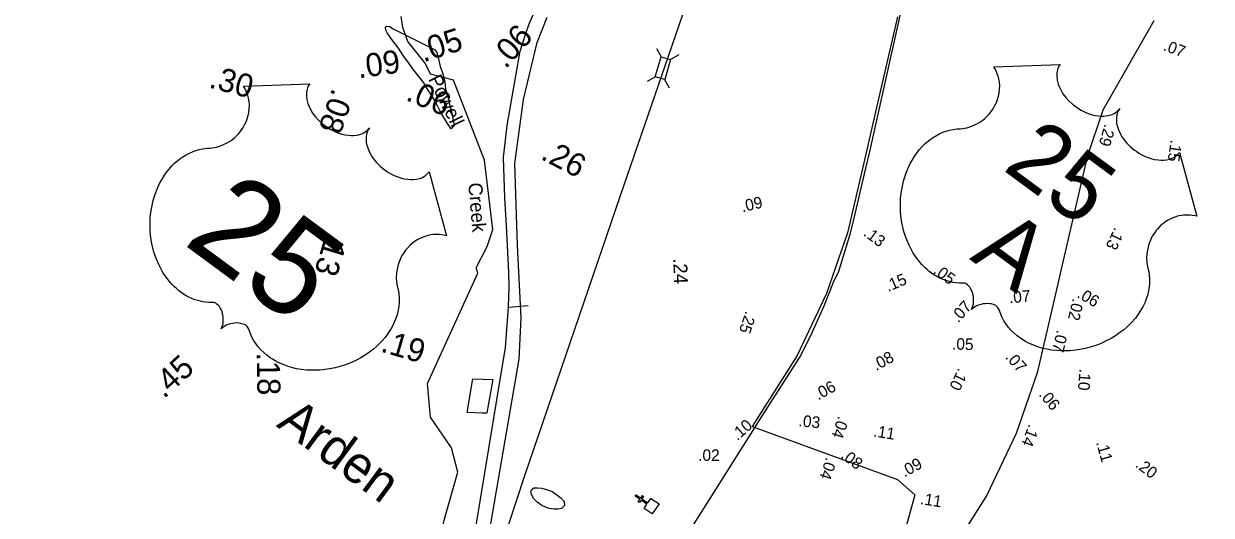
# Model space of a CAD drawing. Extents: x 945666 to 965748, y 644452 to 663300.
# Drawn here: x 952913 to 953745, y 658250 to 658594 of the extents above; entities that cross this region are included whole.
import ezdxf

# ---------------------------------------------------------------- set-up
doc = ezdxf.new("R2010")
doc.units = 0
for name, color, linetype in [('Exist Boundary Political City Limit New', 7, 'Continuous'), ('Exist Civil Demographics Community Label', 7, 'Continuous'), ('Exist Cultural Church CELL', 7, 'Continuous'), ('Exist Hydrographic Creek Single Shore', 7, 'Continuous'), ('Exist Hydrographic Pond Under 1500 Sq Ft', 7, 'Continuous'), ('Exist Railroad Mainline', 7, 'Continuous'), ('Exist Railroad Structure Bridge CELL', 7, 'Continuous'), ('Exist Road Primary US Mileage Hundredths English Label', 7, 'Continuous'), ('Exist Road Primary US Shield Number Label', 7, 'Continuous'), ('Exist Road Primary US UnDivided 4 Lane Attributed', 7, 'Continuous'), ('Exist Road Secondary Mileage Tenths English Label', 7, 'Continuous'), ('Exist Road Secondary Type 51 Attributed', 7, 'Continuous'), ('Old_Level_28', 7, 'Continuous'), ('Old_Level_38', 7, 'Continuous'), ('Prop Paved Shoulder', 7, 'Continuous'), ('Prop Terminator CELL', 7, 'Continuous'), ('Sheet Data Field CELL', 7, 'Continuous'), ('Sheet Sticker Preliminary CELL', 7, 'Continuous')]:
    doc.layers.add(name, color=color, linetype=linetype)

msp = doc.modelspace()

# ---------------------------------------------------------------- linework, layer by layer
at = {"layer": 'Exist Boundary Political City Limit New'}
for points in [[(953263.12, 658541.05), (953272.81, 658580.93), (953279.76, 658598.69)], [(953525.19, 658598.82), (953510.51, 658535.42), (953500.87, 658493.71), (953490.2, 658447.52), (953475.42, 658405.1), (953454.75, 658361.83), (953423.26, 658311.91), (953525.18, 658274.81), (953537.38, 658264.09), (953479.25, 658052.67)], [(952933.88, 658068.96), (952931.53, 658090.74), (952927.54, 658117.68), (952929.12, 658128.44), (952952.22, 658210.11), (952959.47, 658214.17), (952967.28, 658211.36), (952980.47, 658209.98), (952993.63, 658210.79), (953006.46, 658213.79), (953018.89, 658218.94), (953036.71, 658221.84), (953046.85, 658219.95), (953208.62, 658177.89), (953226.42, 658171.6), (953231.84, 658194.97), (953260.2, 658359.21), (953261.51, 658388.04), (953258.98, 658438.73), (953257.1, 658496.31), (953263.12, 658541.05)], [(953234.25, 658321.21), (953223.71, 658321.7), (953227.65, 658345.29), (953241.63, 658344.83), (953238.23, 658325.57), (953237.49, 658321.36), (953235.03, 658321.23), (953234.25, 658321.21)]]:
    msp.add_lwpolyline(points, dxfattribs=at)
at = {"layer": 'Exist Cultural Church CELL'}
msp.add_lwpolyline([(953347.6, 658254.57), (953349.65, 658257.65), (953345.54, 658260.4), (953344.38, 658258.67), (953343.52, 658259.25), (953344.68, 658260.98), (953341.43, 658263.15), (953342.01, 658264.01), (953345.25, 658261.84), (953346.41, 658263.57), (953347.27, 658262.99), (953346.12, 658261.26), (953350.23, 658258.52), (953352.32, 658261.63), (953358.07, 658257.79), (953353.35, 658250.73)], close=True, dxfattribs=at)
at = {"layer": 'Exist Hydrographic Creek Single Shore'}
msp.add_lwpolyline([(953063.7, 657977.16), (953087.98, 657995.59), (953140.42, 658026.77), (953183.23, 658077.19), (953184.97, 658148.97), (953194.07, 658172.62), (953197.29, 658197.56), (953204.73, 658213.89), (953207.17, 658244.8), (953217.23, 658280.09), (953212.7, 658297.01), (953198, 658318.53), (953195.99, 658342.12), (953231.11, 658419.41), (953229.87, 658423.06), (953237.62, 658438.07), (953241.62, 658450.05), (953235.89, 658498.53), (953214.05, 658554.58), (953198.03, 658558.74), (953194.31, 658566.38), (953182.03, 658581.59), (953178.6, 658591.53), (953177.37, 658599.15)], dxfattribs=at)
at = {"layer": 'Exist Hydrographic Pond Under 1500 Sq Ft'}
for points in [[(953212.39, 658520.58), (953210.01, 658524.14), (953205.33, 658532.03), (953201.51, 658539.29), (953198.79, 658543.95), (953195.98, 658548.26), (953193.21, 658552.76), (953189.88, 658557.25), (953186.35, 658561.68), (953182.86, 658566.51), (953178.81, 658571.79), (953175.6, 658577.05), (953170.82, 658583.08), (953167.51, 658587.79), (953166.67, 658589.5), (953166.56, 658591.52), (953167.19, 658592.33), (953169.54, 658592.25), (953171.4, 658590.82), (953177.46, 658587.66)], [(953177.46, 658587.66), (953200.68, 658576.04), (953202.43, 658574.06), (953203.3, 658570.37), (953204.66, 658564.16), (953206.34, 658559.64), (953208.01, 658553.42), (953208.51, 658548.53), (953210.5, 658541.4), (953211.63, 658536.66), (953212.7, 658532.61), (953213.67, 658527.56), (953214.41, 658524.41), (953214.85, 658523.22), (953212.39, 658520.58)], [(953272.82, 658259.06), (953270.32, 658261.42), (953268.76, 658264.34), (953268.33, 658266.38), (953269.04, 658267.78), (953270.49, 658269.04), (953273.04, 658269), (953276, 658268.87), (953279.91, 658267.59), (953283.28, 658266.52), (953286.58, 658264.18), (953289.56, 658261.89), (953291.65, 658259.42), (953291.75, 658256.55), (953289.71, 658254.46), (953287.08, 658254.13), (953284.42, 658254.02), (953281.05, 658254.46), (953278.06, 658255.68), (953276.09, 658256.55), (953272.82, 658259.06)]]:
    msp.add_lwpolyline(points, dxfattribs=at)
at = {"layer": 'Exist Railroad Mainline'}
msp.add_lwpolyline([(953496.77, 658849.77), (953439.11, 658766.27), (953434.45, 658759.1), (953428.22, 658747.98), (953424.48, 658740.75), (953419.55, 658730.34), (953416.53, 658722.78), (953415.54, 658719.88), (953330.81, 658473.62), (953263.93, 658277.51), (953252.36, 658242.54), (953250.06, 658235.49), (953248.62, 658228.64), (953246.69, 658221.95), (953244.11, 658211.67), (953241.48, 658199.5)], dxfattribs=at)
at = {"layer": 'Exist Railroad Structure Bridge CELL'}
for p, q in [((953356.4, 658576.86), (953359.61, 658571)), ((953372.03, 658572.29), (953366.17, 658569.08)), ((953355.61, 658556.91), (953349.75, 658553.71)), ((953362.03, 658555.04), (953365.24, 658549.18))]:
    msp.add_line(p, q, dxfattribs=at)
msp.add_lwpolyline([(953366.17, 658569.08), (953362.06, 658555.03), (953355.5, 658556.95), (953359.61, 658571)], close=True, dxfattribs=at)
at = {"layer": 'Exist Road Primary US UnDivided 4 Lane Attributed'}
msp.add_line((953503.02, 658492.92), (953506, 658505.53), dxfattribs=at)
for points in [[(953257.84, 658557.66), (953260.82, 658574.81), (953264.56, 658586.6), (953267.02, 658594.06), (953296.49, 658660.23), (953306.25, 658683.27), (953312.16, 658695.11), (953317.78, 658708.11), (953323.45, 658724.35), (953327.83, 658739.61), (953334.9, 658765.48), (953345.72, 658806.06), (953355.87, 658833.24), (953359.65, 658840.96), (953367.9, 658854.73), (953374.86, 658865.19)], [(953506, 658505.53), (953527.07, 658599.84), (953532.9, 658619.39), (953536.27, 658627.4), (953540.91, 658638.87), (953549.23, 658655.92), (953562.23, 658676.57), (953571.84, 658691.56)], [(953252.71, 658395.51), (953253.07, 658409.99), (953252.81, 658420.18), (953251.21, 658452.52), (953250.14, 658472.1), (953249.05, 658500.45), (953251.74, 658522.86), (953257.84, 658557.66)], [(953492.04, 658446.74), (953493.91, 658453.87), (953503.02, 658492.92)], [(953456.81, 658360.46), (953464.15, 658375.37), (953473.75, 658396.59), (953480.23, 658413.13), (953484.08, 658420.7), (953492.04, 658446.74)], [(953217.52, 658179.86), (953227.19, 658225.7), (953244.62, 658332.14), (953250.58, 658367.23), (953252.71, 658395.51)], [(953294.18, 658032.4), (953306.83, 658068.42), (953342.91, 658167.72), (953346.11, 658175.59), (953349.13, 658183.21), (953351.97, 658190.72), (953354.53, 658196.94), (953357.04, 658201.72), (953360.38, 658207.22), (953364.52, 658214.99), (953391, 658257.16), (953414.16, 658293.67), (953430.53, 658319.66), (953456.81, 658360.46)]]:
    msp.add_lwpolyline(points, dxfattribs=at)
at = {"layer": 'Exist Road Secondary Type 51 Attributed'}
msp.add_lwpolyline([(953252.71, 658395.51), (953266.42, 658396.75)], dxfattribs=at)
at = {"layer": 'Old_Level_28'}
msp.add_lwpolyline([(953704.85, 658596.15), (953669.11, 658533.48), (953658.09, 658500.8), (953643.41, 658437.4), (953633.77, 658395.69), (953623.1, 658349.5), (953608.33, 658307.08), (953587.66, 658263.81), (953556.16, 658213.89)], dxfattribs=at)
at = {"layer": 'Prop Terminator CELL'}
for points in [[(953639.1, 658565.56), (953638.28, 658564.3), (953637.52, 658562.65), (953637.2, 658561.74), (953636.83, 658559.83), (953636.7, 658557.34), (953637.03, 658554.56), (953637.72, 658551.85), (953638.33, 658550.22), (953639.53, 658547.68), (953641.09, 658545.07), (953643.08, 658542.48), (953645.26, 658540.07), (953647.85, 658537.69), (953650.59, 658535.59), (953653.75, 658533.6), (953657.54, 658531.79), (953659.36, 658531.06), (953661.5, 658530.39), (953663.57, 658529.87), (953666, 658529.52), (953668.06, 658529.38), (953669.74, 658529.37), (953672.39, 658529.71), (953674.76, 658530.34), (953675.91, 658530.82), (953676.97, 658531.32), (953678.88, 658532.62), (953679.63, 658533.27), (953680.94, 658534.8), (953680.04, 658533.37), (953679.56, 658532.42), (953679.17, 658531.43), (953678.87, 658530.29), (953678.57, 658528.59), (953678.5, 658527.05), (953678.67, 658524.55), (953678.92, 658523.19), (953679.21, 658522.04), (953680.19, 658519.22), (953681.64, 658516.33), (953682.41, 658514.99), (953683.28, 658513.71), (953684.43, 658512.17), (953685.7, 658510.67), (953687.03, 658509.29), (953688.42, 658507.93), (953689.91, 658506.63), (953691.18, 658505.65), (953692.78, 658504.49), (953694.31, 658503.5), (953695.94, 658502.56), (953697.8, 658501.62), (953699.34, 658500.93), (953701.45, 658500.1), (953703.45, 658499.5), (953705.3, 658499.07), (953707.81, 658498.69), (953709.95, 658498.52), (953711.66, 658498.59), (953713.8, 658498.83), (953716.04, 658499.33), (953717.49, 658499.83), (953718.77, 658500.51), (953720.05, 658501.27), (953721.2, 658502.24), (953722.09, 658503.16), (953722.76, 658504), (953734.81, 658459.2), (953733.93, 658459.44), (953731.77, 658459.83), (953729.96, 658460.02), (953726.91, 658460.09), (953725.47, 658459.95), (953724.01, 658459.77), (953722.58, 658459.49), (953721.28, 658459.2), (953719.57, 658458.65), (953717.95, 658458.03), (953716.25, 658457.29), (953714.88, 658456.57), (953712.25, 658454.88), (953710.73, 658453.71), (953709.52, 658452.66), (953707.26, 658450.31), (953706.25, 658449.13), (953705.35, 658447.9), (953704.46, 658446.56), (953703.67, 658445.22), (953702.94, 658443.77), (953702.3, 658442.47), (953701.64, 658440.81), (953700.96, 658438.8), (953700.44, 658436.76), (953699.9, 658433.24), (953699.71, 658429.39), (953699.86, 658427.03), (953700.15, 658424.9), (953700.84, 658422.05), (953701.18, 658420.47), (953701.47, 658418.52), (953701.73, 658415.05), (953701.74, 658413.5), (953701.66, 658411.83), (953701.5, 658410.16), (953701.27, 658408.41), (953701.02, 658406.91), (953700.2, 658403.66), (953699.16, 658400.67), (953698.56, 658399.14), (953696.99, 658395.87), (953696.15, 658394.3), (953694.31, 658391.34), (953691.83, 658387.95), (953689.2, 658384.93), (953685.84, 658381.63), (953683.68, 658379.76), (953680.99, 658377.72), (953678.58, 658376.01), (953674.79, 658373.66), (953671.83, 658372.12), (953668.2, 658370.42), (953665.89, 658369.49), (953663.32, 658368.56), (953660.23, 658367.59), (953656.78, 658366.67), (953652.88, 658365.89), (953649.85, 658365.43), (953646.07, 658365.08), (953643.85, 658364.95), (953640.79, 658364.92), (953636.78, 658365.11), (953632.99, 658365.53), (953629.88, 658366.04), (953627.24, 658366.66), (953623.93, 658367.58), (953618.74, 658369.57), (953616.93, 658370.4), (953614.86, 658371.5), (953612.99, 658372.61), (953611.22, 658373.75), (953608.95, 658375.43), (953606.81, 658377.27), (953604.9, 658379.16), (953603.02, 658381.27), (953601.2, 658383.67), (953599.7, 658386.06), (953598.34, 658388.69), (953596.4, 658393.64), (953595.77, 658394.96), (953595.29, 658395.54), (953593.95, 658396.64), (953592.43, 658397.33), (953590.69, 658397.79), (953589.56, 658397.96), (953587.96, 658398.05), (953586.65, 658398), (953584.95, 658397.79), (953583.68, 658397.5), (953582.69, 658397.27), (953580.49, 658396.42), (953579.57, 658395.92), (953578.46, 658395.22), (953577.06, 658394.02), (953577.95, 658396.19), (953578.31, 658397.79), (953578.45, 658399.28), (953578.48, 658400.67), (953578.32, 658402.6), (953578.06, 658404.15), (953577.62, 658405.86), (953576.97, 658407.44), (953576.38, 658408.61), (953575.76, 658409.58), (953574.9, 658410.61), (953574.09, 658411.32), (953573.37, 658411.82), (953572.23, 658412.32), (953570.21, 658412.34), (953568.32, 658412.4), (953566.34, 658412.56), (953564.08, 658412.89), (953562.48, 658413.22), (953560.66, 658413.71), (953558.6, 658414.38), (953556.46, 658415.23), (953554.34, 658416.23), (953552.53, 658417.17), (953550.68, 658418.3), (953549.07, 658419.4), (953547.44, 658420.63), (953546, 658421.88), (953544.33, 658423.35), (953542.37, 658425.31), (953540.84, 658427.07), (953539.29, 658429.01), (953537.77, 658431.09), (953536.25, 658433.47), (953534.44, 658436.59), (953533.3, 658438.9), (953531.62, 658442.72), (953529.94, 658447.6), (953528.91, 658451.59), (953528.28, 658454.7), (953527.59, 658459.57), (953527.32, 658462.62), (953527.2, 658467.83), (953527.33, 658471.43), (953527.57, 658473.98), (953528.1, 658477.95), (953528.56, 658480.36), (953529.37, 658483.76), (953530.24, 658486.77), (953531.17, 658489.55), (953531.84, 658491.27), (953533.13, 658494.18), (953534.11, 658496.2), (953535.57, 658498.88), (953537.29, 658501.58), (953539, 658503.97), (953540.51, 658505.89), (953542.43, 658508.02), (953544.61, 658510.17), (953546.62, 658511.92), (953548.15, 658513.11), (953550.12, 658514.48), (953552.42, 658515.89), (953554.82, 658517.11), (953556.92, 658518.04), (953559.35, 658518.91), (953561.57, 658519.54), (953564.26, 658520.06), (953566.91, 658520.4), (953569.18, 658520.51), (953572.1, 658520.92), (953573.71, 658521.27), (953575.81, 658521.88), (953577.61, 658522.55), (953579.13, 658523.21), (953581.28, 658524.27), (953582.76, 658525.15), (953584.88, 658526.62), (953586.24, 658527.75), (953587.89, 658529.28), (953589.35, 658530.79), (953590.98, 658532.81), (953592.2, 658534.58), (953593.46, 658536.76), (953594.51, 658538.97), (953595.3, 658541), (953596, 658543.47), (953596.38, 658545.37), (953596.67, 658548.12), (953596.74, 658550.81), (953596.52, 658553.21), (953596.18, 658555.46), (953595.66, 658557.34), (953595.1, 658559.06), (953594.28, 658561.05), (953593.37, 658562.81), (953592.73, 658563.84)], [(953113.43, 658552), (953112.61, 658550.74), (953111.85, 658549.09), (953111.52, 658548.18), (953111.15, 658546.27), (953111.02, 658543.78), (953111.36, 658541.01), (953112.04, 658538.29), (953112.65, 658536.66), (953113.86, 658534.12), (953115.42, 658531.51), (953117.4, 658528.93), (953119.59, 658526.51), (953122.17, 658524.13), (953124.91, 658522.03), (953128.08, 658520.04), (953131.86, 658518.23), (953133.69, 658517.5), (953135.83, 658516.83), (953137.9, 658516.31), (953140.33, 658515.96), (953142.39, 658515.83), (953144.07, 658515.81), (953146.72, 658516.15), (953149.08, 658516.78), (953150.24, 658517.26), (953151.3, 658517.76), (953153.21, 658519.07), (953153.95, 658519.72), (953155.27, 658521.24), (953154.37, 658519.81), (953153.88, 658518.86), (953153.5, 658517.87), (953153.19, 658516.73), (953152.9, 658515.03), (953152.82, 658513.49), (953152.99, 658510.99), (953153.24, 658509.63), (953153.54, 658508.48), (953154.52, 658505.66), (953155.97, 658502.77), (953156.74, 658501.43), (953157.61, 658500.15), (953158.76, 658498.61), (953160.03, 658497.12), (953161.36, 658495.74), (953162.74, 658494.37), (953164.24, 658493.08), (953165.51, 658492.09), (953167.11, 658490.93), (953168.64, 658489.94), (953170.27, 658489), (953172.13, 658488.06), (953173.67, 658487.37), (953175.77, 658486.54), (953177.78, 658485.94), (953179.62, 658485.51), (953182.13, 658485.13), (953184.27, 658484.96), (953185.98, 658485.04), (953188.12, 658485.27), (953190.36, 658485.77), (953191.82, 658486.27), (953193.1, 658486.96), (953194.38, 658487.72), (953195.53, 658488.68), (953196.42, 658489.6), (953197.09, 658490.45), (953209.13, 658445.64), (953208.25, 658445.88), (953206.09, 658446.28), (953204.29, 658446.46), (953201.23, 658446.53), (953199.8, 658446.39), (953198.34, 658446.21), (953196.91, 658445.94), (953195.61, 658445.64), (953193.9, 658445.09), (953192.27, 658444.47), (953190.58, 658443.73), (953189.21, 658443.01), (953186.58, 658441.32), (953185.05, 658440.16), (953183.85, 658439.1), (953181.58, 658436.75), (953180.58, 658435.57), (953179.67, 658434.34), (953178.79, 658433), (953177.99, 658431.67), (953177.26, 658430.21), (953176.63, 658428.91), (953175.96, 658427.25), (953175.28, 658425.25), (953174.76, 658423.2), (953174.23, 658419.68), (953174.03, 658415.83), (953174.19, 658413.47), (953174.48, 658411.34), (953175.16, 658408.49), (953175.5, 658406.91), (953175.79, 658404.96), (953176.06, 658401.49), (953176.06, 658399.94), (953175.98, 658398.27), (953175.82, 658396.6), (953175.6, 658394.85), (953175.35, 658393.36), (953174.53, 658390.1), (953173.48, 658387.11), (953172.88, 658385.58), (953171.31, 658382.31), (953170.48, 658380.74), (953168.64, 658377.78), (953166.15, 658374.39), (953163.53, 658371.38), (953160.16, 658368.08), (953158.01, 658366.2), (953155.32, 658364.16), (953152.91, 658362.45), (953149.12, 658360.1), (953146.15, 658358.56), (953142.53, 658356.86), (953140.22, 658355.93), (953137.64, 658355), (953134.55, 658354.03), (953131.11, 658353.11), (953127.21, 658352.33), (953124.18, 658351.87), (953120.4, 658351.52), (953118.18, 658351.4), (953115.12, 658351.36), (953111.1, 658351.55), (953107.31, 658351.97), (953104.2, 658352.48), (953101.57, 658353.1), (953098.25, 658354.02), (953093.06, 658356.01), (953091.25, 658356.84), (953089.18, 658357.94), (953087.31, 658359.05), (953085.55, 658360.19), (953083.27, 658361.87), (953081.14, 658363.71), (953079.23, 658365.6), (953077.35, 658367.71), (953075.53, 658370.12), (953074.02, 658372.5), (953072.66, 658375.13), (953070.73, 658380.08), (953070.09, 658381.4), (953069.62, 658381.99), (953068.27, 658383.09), (953066.76, 658383.78), (953065.02, 658384.23), (953063.89, 658384.4), (953062.29, 658384.49), (953060.98, 658384.44), (953059.28, 658384.23), (953058, 658383.95), (953057.02, 658383.71), (953054.82, 658382.86), (953053.89, 658382.37), (953052.79, 658381.66), (953051.39, 658380.46), (953052.28, 658382.63), (953052.63, 658384.23), (953052.77, 658385.72), (953052.8, 658387.11), (953052.65, 658389.04), (953052.38, 658390.59), (953051.94, 658392.3), (953051.29, 658393.88), (953050.71, 658395.05), (953050.09, 658396.02), (953049.23, 658397.05), (953048.41, 658397.76), (953047.69, 658398.26), (953046.56, 658398.76), (953044.53, 658398.78), (953042.65, 658398.84), (953040.66, 658399), (953038.4, 658399.33), (953036.81, 658399.66), (953034.98, 658400.15), (953032.92, 658400.82), (953030.78, 658401.68), (953028.67, 658402.67), (953026.86, 658403.61), (953025, 658404.74), (953023.39, 658405.85), (953021.77, 658407.07), (953020.32, 658408.32), (953018.66, 658409.79), (953016.69, 658411.75), (953015.17, 658413.51), (953013.62, 658415.45), (953012.09, 658417.54), (953010.57, 658419.91), (953008.77, 658423.03), (953007.62, 658425.34), (953005.94, 658429.16), (953004.27, 658434.05), (953003.23, 658438.04), (953002.6, 658441.14), (953001.91, 658446.02), (953001.64, 658449.07), (953001.53, 658454.27), (953001.66, 658457.88), (953001.89, 658460.42), (953002.43, 658464.39), (953002.89, 658466.8), (953003.69, 658470.2), (953004.57, 658473.21), (953005.5, 658475.99), (953006.16, 658477.71), (953007.46, 658480.62), (953008.43, 658482.64), (953009.9, 658485.32), (953011.61, 658488.02), (953013.32, 658490.41), (953014.84, 658492.33), (953016.75, 658494.47), (953018.94, 658496.61), (953020.94, 658498.36), (953022.47, 658499.55), (953024.44, 658500.92), (953026.75, 658502.33), (953029.14, 658503.55), (953031.25, 658504.48), (953033.68, 658505.35), (953035.9, 658505.98), (953038.59, 658506.5), (953041.23, 658506.84), (953043.51, 658506.95), (953046.42, 658507.36), (953048.04, 658507.71), (953050.13, 658508.32), (953051.93, 658509), (953053.46, 658509.66), (953055.61, 658510.71), (953057.08, 658511.59), (953059.21, 658513.06), (953060.56, 658514.2), (953062.22, 658515.72), (953063.68, 658517.23), (953065.3, 658519.25), (953066.52, 658521.02), (953067.79, 658523.2), (953068.83, 658525.41), (953069.62, 658527.44), (953070.33, 658529.91), (953070.7, 658531.81), (953071, 658534.56), (953071.07, 658537.25), (953070.85, 658539.65), (953070.51, 658541.9), (953069.98, 658543.78), (953069.42, 658545.5), (953068.6, 658547.49), (953067.69, 658549.25), (953067.06, 658550.28)]]:
    msp.add_lwpolyline(points, close=True, dxfattribs=at)

# ---------------------------------------------------------------- texts
at = {"layer": 'Exist Civil Demographics Community Label'}
msp.add_text('Arden', height=25.981, rotation=323.59084, dxfattribs=at).set_placement((953089.37, 658312.37))
at = {"layer": 'Exist Road Primary US Mileage Hundredths English Label'}
for s, height, rotation, p in [('.29', 8.119, 253.39658, (953670.37, 658524.12)), ('.24', 9.743, 272.18766, (953368, 658429.67)), ('.02', 8.119, 256.72831, (953647.98, 658401.99)), ('.07', 8.119, 256.86158, (953636.86, 658379.89)), ('.14', 8.119, 248.61923, (953617.3, 658313.95))]:
    msp.add_text(s, height=height, rotation=rotation, dxfattribs=at).set_placement(p)
at = {"layer": 'Exist Road Primary US Shield Number Label'}
for s, height, p in [('25', 46.953, (953598.13, 658492.22)), ('25', 66.589, (953023.85, 658440.39)), ('A', 46.95, (953575.12, 658429.44))]:
    msp.add_text(s, height=height, rotation=323.59084, dxfattribs=at).set_placement(p)
at = {"layer": 'Exist Road Secondary Mileage Tenths English Label'}
for s, height, rotation, p in [('.06', 16.238, 48.44644, (953250.58, 658561.97)), ('.05', 16.238, 17.62535, (953193.03, 658567.03)), ('.07', 8.119, 339.94332, (953710.82, 658575.56)), ('.09', 16.238, 8.06663, (953147.69, 658555.8)), ('.30', 16.238, 344.97607, (953042.09, 658549.55)), ('.06', 16.238, 337.0849, (953179.96, 658540.83)), ('.08', 16.238, 250.54543, (953129.38, 658549.47)), ('.26', 16.238, 332.51368, (953274.49, 658499.62)), ('.15', 8.119, 261.8001, (953716.61, 658513.02)), ('.13', 16.238, 253.07134, (953125.29, 658449.32)), ('.13', 8.119, 323.11441, (953500.7, 658446.23)), ('.13', 8.119, 243.99274, (953677.46, 658451.82)), ('.15', 8.119, 23.22898, (953518.57, 658406.15)), ('.05', 8.119, 323.44347, (953549.73, 658419.79)), ('.07', 8.119, 4.86016, (953603.58, 658398.28)), ('.06', 8.119, 329.91458, (953650.41, 658402.75)), ('.07', 8.119, 47.94155, (953567.67, 658384.25)), ('.25', 8.119, 251.06579, (953418.88, 658393.15)), ('.19', 16.238, 343.76817, (953162.41, 658364.59)), ('.05', 8.119, 358.34135, (953563.27, 658365.92)), ('.45', 16.238, 42.37109, (953011.22, 658331.11)), ('.18', 16.238, 271.14633, (953076.17, 658363.87)), ('.08', 8.119, 28.96067, (953510.27, 658350.79)), ('.07', 8.119, 312.13878, (953600.24, 658360.23)), ('.10', 8.119, 243.8589, (953567.92, 658353.35)), ('.10', 8.119, 265.60589, (953652.71, 658352.57)), ('.06', 8.119, 28.82726, (953469.63, 658330.2)), ('.03', 8.119, 353.91806, (953455.57, 658312.26)), ('.04', 8.119, 251.06579, (953483.75, 658319.67)), ('.10', 8.119, 41.32863, (953412.91, 658301.69)), ('.11', 8.119, 350.8761, (953507.85, 658305.04)), ('.02', 8.119, 359.51477, (953385.47, 658287.92)), ('.08', 8.119, 322.44351, (953484.84, 658290.54)), ('.04', 8.119, 251.06579, (953475.28, 658290.8)), ('.09', 8.119, 28.41713, (953530.04, 658276.24)), ('.20', 8.119, 322.45419, (953691.26, 658284.13)), ('.11', 8.119, 350.8761, (953540.65, 658257.73))]:
    msp.add_text(s, height=height, rotation=rotation, dxfattribs=at).set_placement(p)
at = {"layer": 'Old_Level_38'}
msp.add_text('VICINITY MAP', height=150, rotation=323.59084, dxfattribs=at).set_placement((952391.64, 658186.9))
at = {"layer": 'Prop Paved Shoulder'}
for s, rotation, p in [('Powell', 296.31478, (953196.21, 658555.38)), ('Creek', 274.97255, (953224.38, 658482.4))]:
    msp.add_text(s, height=9.743, rotation=rotation, dxfattribs=at).set_placement(p)
at = {"layer": 'Sheet Data Field CELL'}
for s, p in [('1. DESIGN EXCEPTIONS FOR VERTICAL CURVE K VALUE', (951636.01, 658445.97)), (' AND STOPPING SIGHT DISTANCE HAVE BEEN REQUESTED', (951567.93, 658353.65))]:
    msp.add_text(s, height=87.501, rotation=323.59084, dxfattribs=at).set_placement(p)
at = {"layer": 'Sheet Sticker Preliminary CELL'}
for s, rotation, p in [('.09', 12.99725, (953416.54, 658462.06)), ('.06', 310.01463, (953623.77, 658334.06)), ('.11', 285.47676, (953664.28, 658300.81))]:
    msp.add_text(s, height=8.119, rotation=rotation, dxfattribs=at).set_placement(p)

doc.saveas('drawing.dxf')
